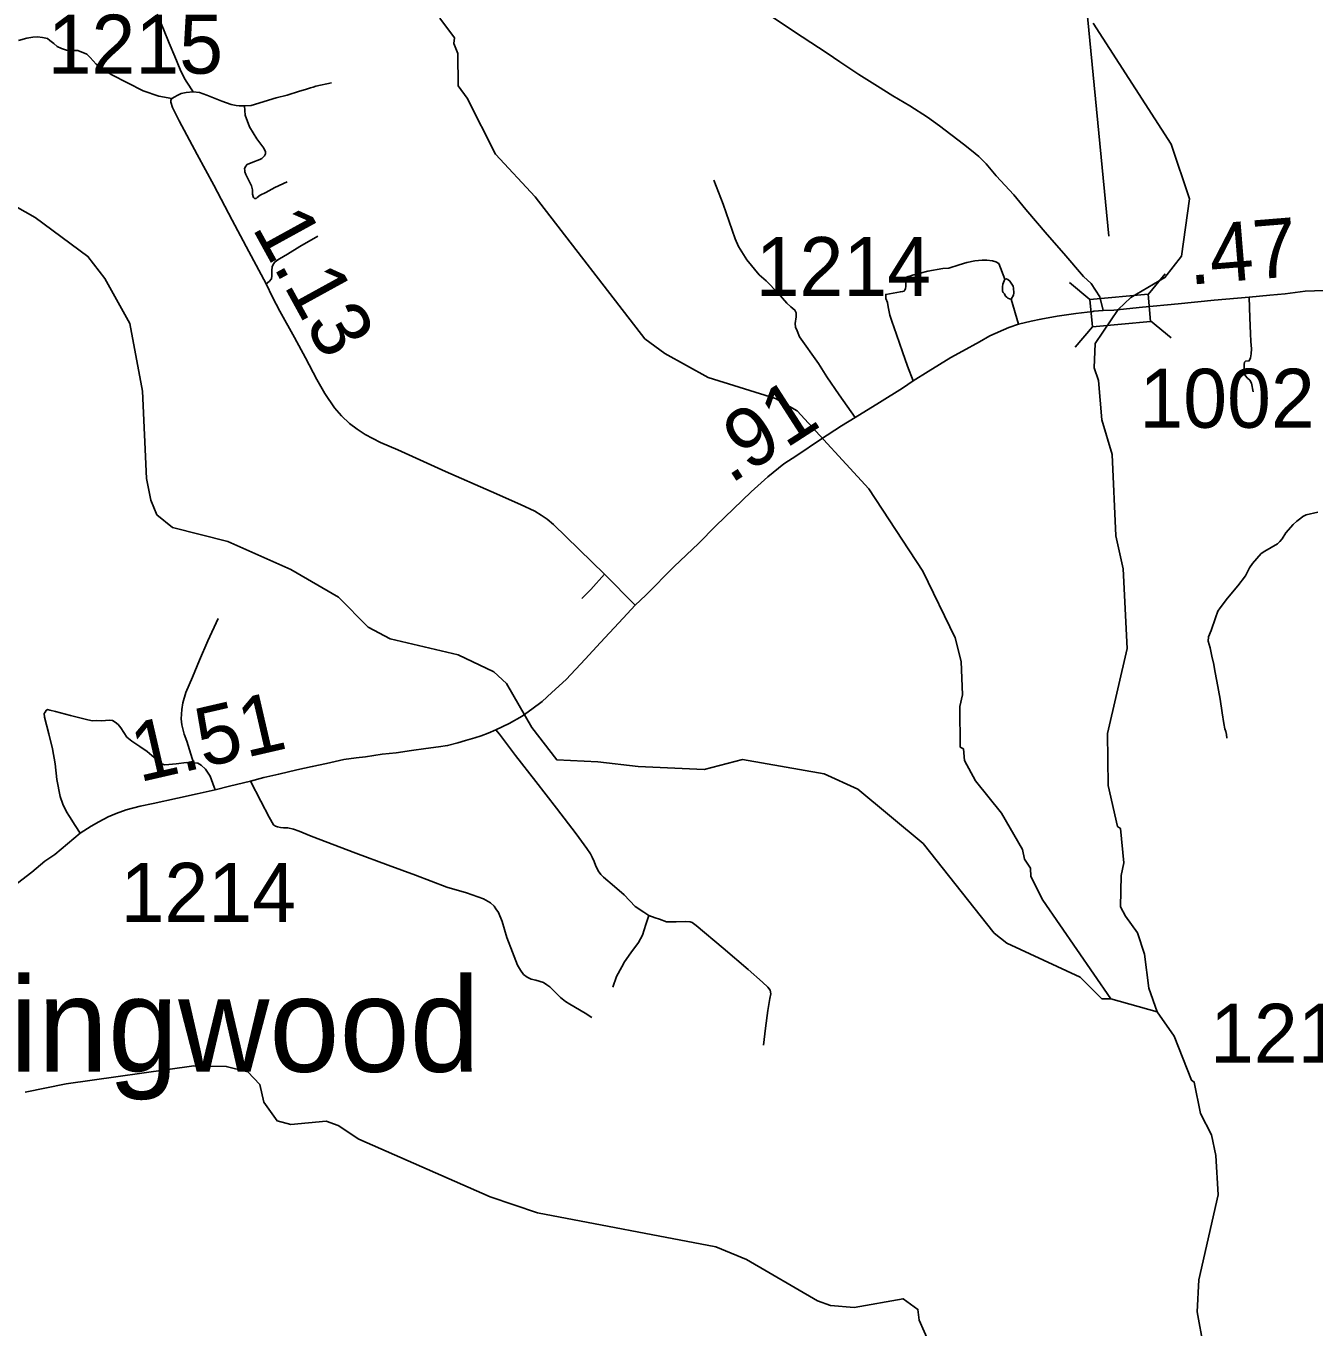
# Model space of a CAD drawing. Extents: x 2290615 to 2522933, y 819489 to 1012715.
# Drawn here: x 2342087 to 2353015, y 894770 to 905808 of the extents above; entities that cross this region are included whole.
import ezdxf

# ---------------------------------------------------------------- set-up
doc = ezdxf.new("R2010")
doc.units = 0
for name, color, linetype in [('Exist Civil Demographics Community Label', 7, 'Continuous'), ('Exist Hydrographic Creek Single Shore', 7, 'Continuous'), ('Exist Hydrographic Misc Water Feature', 7, 'Continuous'), ('Exist Road Non-System Type 51', 7, 'Continuous'), ('Exist Road Secondary Mileage Hundredths English Label', 7, 'Continuous'), ('Exist Road Secondary Structure Standard Bridge CELL', 7, 'Continuous'), ('Exist Road Secondary Structure Standard Bridge Number Label', 7, 'Continuous'), ('Exist Road Secondary Type 51 Attributed', 7, 'Continuous'), ('Exist Road Secondary Type 51 Number Label', 7, 'Continuous')]:
    doc.layers.add(name, color=color, linetype=linetype)

msp = doc.modelspace()

# ---------------------------------------------------------------- linework, layer by layer
at = {"layer": 'Exist Hydrographic Creek Single Shore'}
for points in [[(2351677, 897449), (2351607, 897650), (2351571, 897940), (2351510, 898121), (2351408, 898262), (2351366, 898339), (2351371, 898605), (2351395, 898714), (2351366, 899005), (2351341, 899021), (2351262, 899368), (2351257, 899811), (2351423, 900531), (2351390, 901205), (2351328, 901485), (2351295, 902176), (2351208, 902468), (2351179, 902802), (2351144, 902909), (2351150, 903116), (2351345, 903405), (2351454, 903506), (2351743, 903675), (2351883, 903858), (2351952, 904343), (2351796, 904806), (2351134, 905833)], [(2352206, 894290), (2352102, 894591), (2352069, 894613), (2352015, 894906), (2352029, 895179), (2352195, 895898), (2352174, 896232), (2352139, 896408), (2352045, 896588), (2351992, 896855), (2351967, 896870), (2351820, 897245), (2351677, 897449)], [(2342079, 896770), (2342428, 896840), (2343509, 896993), (2343784, 896987), (2343968, 896942), (2344069, 896835), (2344104, 896685), (2344215, 896526), (2344332, 896494), (2344631, 896523), (2344732, 896485), (2344908, 896370), (2346022, 895881), (2346424, 895747), (2347935, 895457), (2348194, 895350), (2348798, 895000), (2348907, 894959), (2349107, 894944), (2349523, 895017), (2349649, 894927), (2349659, 894835), (2349744, 894645)]]:
    msp.add_lwpolyline(points, dxfattribs=at)
at = {"layer": 'Exist Hydrographic Misc Water Feature'}
msp.add_line((2351677, 897449), (2351284, 897561), dxfattribs=at)
for points in [[(2351284, 897561), (2350707, 898397), (2350605, 898596), (2350604, 898669), (2350553, 898745), (2350535, 898827), (2350357, 899134), (2350137, 899408), (2350043, 899581), (2350034, 899679), (2350008, 899695), (2350004, 900039), (2350028, 900138), (2350016, 900420), (2349964, 900622), (2349690, 901185), (2349232, 901885), (2348624, 902546), (2348440, 902650), (2347871, 902827), (2347502, 903032), (2347334, 903156), (2346403, 904359), (2346066, 904722), (2345827, 905195), (2345751, 905300), (2345747, 905576), (2345713, 905660), (2345720, 905709), (2345594, 905875)], [(2351284, 897561), (2351208, 897561), (2351023, 897744), (2350403, 898033), (2350294, 898118), (2349693, 898877), (2349138, 899337), (2348853, 899467), (2348160, 899589), (2347836, 899504), (2347278, 899530), (2346936, 899569), (2346586, 899587), (2346374, 899861), (2346161, 900233), (2346052, 900333), (2345750, 900478), (2345174, 900612), (2344989, 900710), (2344736, 900965), (2344333, 901201), (2343798, 901439), (2343329, 901557), (2343195, 901664), (2343144, 901789), (2343108, 901972), (2343074, 902712), (2342967, 903285), (2342754, 903667), (2342611, 903855), (2342165, 904185), (2341804, 904387)]]:
    msp.add_lwpolyline(points, dxfattribs=at)
at = {"layer": 'Exist Road Non-System Type 51'}
msp.add_line((2350501, 903280), (2350440, 903491), dxfattribs=at)
msp.add_line((2350501, 903280), (2350440, 903491), dxfattribs=at)
for points in [[(2343199, 905909), (2343253, 905780), (2343300, 905662), (2343349, 905549), (2343393, 905440), (2343430, 905364), (2343450, 905332), (2343504, 905249)], [(2343322, 905193), (2343212, 905214), (2343081, 905258), (2342948, 905325), (2342814, 905395), (2342719, 905454), (2342681, 905485), (2342632, 905541), (2342603, 905570), (2342525, 905601), (2342479, 905601), (2342431, 905602), (2342387, 905616), (2342351, 905635), (2342323, 905659), (2342290, 905684), (2342268, 905702), (2342226, 905712), (2342184, 905717), (2342144, 905713), (2342094, 905704), (2342024, 905685)], [(2343504, 905249), (2343445, 905245), (2343402, 905235), (2343369, 905220), (2343348, 905208), (2343322, 905193)], [(2343504, 905249), (2343445, 905245), (2343402, 905235), (2343369, 905220), (2343348, 905208), (2343322, 905193)], [(2343939, 905130), (2343893, 905131), (2343869, 905133), (2343826, 905143), (2343746, 905170), (2343620, 905222), (2343557, 905244), (2343504, 905249)], [(2343939, 905130), (2343893, 905131), (2343869, 905133), (2343826, 905143), (2343746, 905170), (2343620, 905222), (2343557, 905244), (2343504, 905249)], [(2344677, 905326), (2344544, 905298), (2344520, 905289), (2344499, 905284), (2344456, 905269), (2344405, 905256), (2344301, 905223), (2344208, 905198), (2343995, 905133), (2343939, 905130)], [(2344677, 905326), (2344544, 905298), (2344520, 905289), (2344499, 905284), (2344456, 905269), (2344405, 905256), (2344301, 905223), (2344208, 905198), (2343995, 905133), (2343939, 905130)], [(2343322, 905193), (2343315, 905180), (2343314, 905163), (2343328, 905116)], [(2343322, 905193), (2343315, 905180), (2343314, 905163), (2343328, 905116)], [(2344300, 904487), (2344197, 904440), (2344119, 904397), (2344072, 904373), (2344048, 904353), (2344038, 904347), (2344031, 904346), (2344023, 904347), (2344016, 904353), (2344012, 904364), (2344006, 904382), (2344006, 904420), (2343998, 904453), (2343977, 904498), (2343951, 904549), (2343943, 904571), (2343941, 904586), (2343940, 904598), (2343948, 904618), (2343961, 904634), (2344010, 904655), (2344068, 904676), (2344086, 904686), (2344100, 904698), (2344108, 904706), (2344113, 904712), (2344118, 904725), (2344118, 904742), (2344102, 904772), (2344045, 904852), (2343981, 904953), (2343944, 905051), (2343939, 905130)], [(2347917, 904502), (2347997, 904299), (2348100, 904005), (2348128, 903939), (2348199, 903827), (2348302, 903699), (2348362, 903649), (2348465, 903543), (2348537, 903457), (2348572, 903426), (2348606, 903399), (2348616, 903377), (2348615, 903343), (2348607, 903287), (2348610, 903255), (2348624, 903223), (2348646, 903174), (2348807, 902946), (2348875, 902834), (2348980, 902681), (2349117, 902489)], [(2344561, 904026), (2344407, 903940), (2344305, 903873), (2344235, 903834), (2344212, 903819), (2344196, 903806), (2344185, 903792), (2344175, 903765), (2344171, 903735), (2344171, 903690), (2344167, 903665), (2344148, 903643), (2344122, 903621)], [(2350386, 903662), (2350334, 903794), (2350310, 903809), (2350282, 903817), (2350234, 903822), (2350192, 903824), (2350132, 903817), (2350064, 903804), (2349997, 903783), (2349911, 903755), (2349859, 903752), (2349733, 903730), (2349602, 903695), (2349581, 903687), (2349567, 903684), (2349553, 903678), (2349548, 903675), (2349545, 903671), (2349544, 903661), (2349545, 903646), (2349546, 903625), (2349547, 903602), (2349542, 903580), (2349538, 903570), (2349532, 903561), (2349519, 903557), (2349500, 903555), (2349438, 903542), (2349376, 903533), (2349378, 903499), (2349391, 903464), (2349395, 903426), (2349410, 903357), (2349427, 903307), (2349467, 903193), (2349517, 903045), (2349561, 902924), (2349609, 902799)], [(2350386, 903662), (2350369, 903620), (2350367, 903596), (2350365, 903578), (2350365, 903560), (2350370, 903548), (2350382, 903536), (2350392, 903518), (2350402, 903508), (2350410, 903500), (2350426, 903495), (2350440, 903491)], [(2350386, 903662), (2350369, 903620), (2350367, 903596), (2350365, 903578), (2350365, 903560), (2350370, 903548), (2350382, 903536), (2350392, 903518), (2350402, 903508), (2350410, 903500), (2350426, 903495), (2350440, 903491)], [(2350440, 903491), (2350458, 903527), (2350461, 903547), (2350459, 903585), (2350457, 903603), (2350440, 903629), (2350428, 903645), (2350410, 903659), (2350398, 903664), (2350386, 903662)], [(2350440, 903491), (2350458, 903527), (2350461, 903547), (2350459, 903585), (2350457, 903603), (2350440, 903629), (2350428, 903645), (2350410, 903659), (2350398, 903664), (2350386, 903662)], [(2352457, 903508), (2352462, 903335), (2352468, 903201), (2352470, 903132), (2352476, 903071), (2352475, 903029), (2352468, 902995), (2352458, 902970), (2352426, 902967), (2352418, 902958), (2352416, 902938), (2352415, 902910), (2352415, 902871), (2352422, 902844), (2352444, 902821), (2352463, 902805), (2352477, 902781), (2352491, 902706)], [(2353040, 901687), (2352941, 901665), (2352912, 901649), (2352894, 901635), (2352862, 901611), (2352830, 901582), (2352769, 901511), (2352738, 901461), (2352716, 901439), (2352696, 901417), (2352591, 901355), (2352559, 901335), (2352484, 901252), (2352459, 901214), (2352426, 901147), (2352361, 901061), (2352272, 900956), (2352210, 900874), (2352191, 900847), (2352172, 900790), (2352135, 900684), (2352111, 900629), (2352110, 900594), (2352127, 900536), (2352141, 900466), (2352157, 900394), (2352166, 900342), (2352184, 900253), (2352211, 900102), (2352228, 899986), (2352243, 899895), (2352252, 899848), (2352259, 899826), (2352264, 899801), (2352267, 899770)], [(2346990, 901160), (2346876, 901032), (2346799, 900955)], [(2343507, 899562), (2343449, 899744), (2343429, 899804), (2343408, 899882), (2343403, 899935), (2343408, 900013), (2343417, 900070), (2343442, 900158), (2343497, 900288), (2343559, 900431), (2343629, 900596), (2343717, 900785)], [(2343507, 899562), (2343449, 899744), (2343429, 899804), (2343408, 899882), (2343403, 899935), (2343408, 900013), (2343417, 900070), (2343442, 900158), (2343497, 900288), (2343559, 900431), (2343629, 900596), (2343717, 900785)], [(2343507, 899562), (2343447, 899563), (2343361, 899554), (2343298, 899546), (2343262, 899544), (2343223, 899558), (2343172, 899605), (2343114, 899657), (2343052, 899700), (2342985, 899745), (2342943, 899780), (2342890, 899859), (2342868, 899885), (2342844, 899905), (2342821, 899921), (2342793, 899922), (2342729, 899918), (2342681, 899919), (2342649, 899918), (2342589, 899932), (2342465, 899962), (2342338, 899997), (2342288, 900008), (2342268, 900012), (2342258, 900006), (2342249, 899992), (2342241, 899978), (2342243, 899948), (2342279, 899806), (2342312, 899681), (2342334, 899553), (2342348, 899419), (2342377, 899275), (2342400, 899212), (2342429, 899146), (2342455, 899105), (2342504, 899029), (2342547, 898964)], [(2343507, 899562), (2343447, 899563), (2343361, 899554), (2343298, 899546), (2343262, 899544), (2343223, 899558), (2343172, 899605), (2343114, 899657), (2343052, 899700), (2342985, 899745), (2342943, 899780), (2342890, 899859), (2342868, 899885), (2342844, 899905), (2342821, 899921), (2342793, 899922), (2342729, 899918), (2342681, 899919), (2342649, 899918), (2342589, 899932), (2342465, 899962), (2342338, 899997), (2342288, 900008), (2342268, 900012), (2342258, 900006), (2342249, 899992), (2342241, 899978), (2342243, 899948), (2342279, 899806), (2342312, 899681), (2342334, 899553), (2342348, 899419), (2342377, 899275), (2342400, 899212), (2342429, 899146), (2342455, 899105), (2342504, 899029), (2342547, 898964)], [(2347368, 898268), (2347324, 898295), (2347251, 898344), (2347158, 898443), (2347077, 898514), (2346984, 898591), (2346960, 898613), (2346939, 898646), (2346915, 898694), (2346903, 898724), (2346888, 898762), (2346872, 898790), (2346843, 898835), (2346750, 898958), (2346585, 899176), (2346409, 899404), (2346236, 899622), (2346101, 899803), (2346071, 899842)], [(2343690, 899332), (2343672, 899387), (2343647, 899447), (2343608, 899507), (2343572, 899540), (2343543, 899559), (2343507, 899562)], [(2346884, 897402), (2346828, 897439), (2346697, 897514), (2346661, 897537), (2346619, 897571), (2346529, 897662), (2346503, 897679), (2346473, 897699), (2346409, 897718), (2346371, 897726), (2346337, 897743), (2346304, 897767), (2346278, 897803), (2346255, 897846), (2346212, 897956), (2346164, 898081), (2346125, 898217), (2346094, 898292), (2346070, 898324), (2346055, 898346), (2346025, 898374), (2345965, 898407), (2345822, 898459), (2345656, 898507), (2345388, 898608), (2345157, 898693), (2344882, 898794), (2344505, 898939), (2344404, 898982), (2344354, 898999), (2344306, 899011), (2344270, 899010), (2344244, 899014), (2344220, 899018), (2344202, 899023), (2344186, 899035), (2344147, 899101), (2344077, 899236), (2343991, 899407)], [(2346884, 897402), (2346828, 897439), (2346697, 897514), (2346661, 897537), (2346619, 897571), (2346529, 897662), (2346503, 897679), (2346473, 897699), (2346409, 897718), (2346371, 897726), (2346337, 897743), (2346304, 897767), (2346278, 897803), (2346255, 897846), (2346212, 897956), (2346164, 898081), (2346125, 898217), (2346094, 898292), (2346070, 898324), (2346055, 898346), (2346025, 898374), (2345965, 898407), (2345822, 898459), (2345656, 898507), (2345388, 898608), (2345157, 898693), (2344882, 898794), (2344505, 898939), (2344404, 898982), (2344354, 898999), (2344306, 899011), (2344270, 899010), (2344244, 899014), (2344220, 899018), (2344202, 899023), (2344186, 899035), (2344147, 899101), (2344077, 899236), (2343991, 899407)], [(2347368, 898268), (2347343, 898191), (2347314, 898101), (2347279, 898037), (2347214, 897950), (2347161, 897873), (2347137, 897831), (2347094, 897749), (2347063, 897660)], [(2347368, 898268), (2347343, 898191), (2347314, 898101), (2347279, 898037), (2347214, 897950), (2347161, 897873), (2347137, 897831), (2347094, 897749), (2347063, 897660)], [(2348339, 897168), (2348355, 897312), (2348377, 897462), (2348392, 897564), (2348402, 897604), (2348397, 897634), (2348377, 897660), (2348330, 897702), (2348209, 897808), (2347997, 897989), (2347769, 898183), (2347736, 898206), (2347717, 898214), (2347682, 898215), (2347598, 898213), (2347556, 898212), (2347518, 898213), (2347458, 898235), (2347420, 898248), (2347368, 898268)], [(2348339, 897168), (2348355, 897312), (2348377, 897462), (2348392, 897564), (2348402, 897604), (2348397, 897634), (2348377, 897660), (2348330, 897702), (2348209, 897808), (2347997, 897989), (2347769, 898183), (2347736, 898206), (2347717, 898214), (2347682, 898215), (2347598, 898213), (2347556, 898212), (2347518, 898213), (2347458, 898235), (2347420, 898248), (2347368, 898268)]]:
    msp.add_lwpolyline(points, dxfattribs=at)
at = {"layer": 'Exist Road Secondary Structure Standard Bridge CELL'}
for p, q in [((2351600, 903533), (2351745, 903707)), ((2350933, 903634), (2351107, 903489)), ((2350983, 903085), (2351128, 903258)), ((2351621, 903308), (2351795, 903163))]:
    msp.add_line(p, q, dxfattribs=at)
msp.add_lwpolyline([(2351107, 903489), (2351600, 903534), (2351621, 903303), (2351128, 903258)], close=True, dxfattribs=at)
at = {"layer": 'Exist Road Secondary Structure Standard Bridge Number Label'}
msp.add_lwpolyline([(2351267, 904026), (2351050, 906271), (2345693, 911628)], dxfattribs=at)
at = {"layer": 'Exist Road Secondary Type 51 Attributed'}
for points in [[(2347791, 906300), (2348666, 905717), (2348878, 905577), (2348986, 905503), (2349148, 905397), (2349305, 905299), (2349436, 905216), (2349581, 905130), (2349730, 905034), (2349833, 904963), (2350035, 904806), (2350104, 904753), (2350165, 904702), (2350227, 904639), (2350312, 904538), (2350461, 904378), (2350564, 904251), (2350744, 904041), (2350886, 903879), (2351052, 903683), (2351118, 903625), (2351191, 903511), (2351219, 903397)], [(2347250, 900898), (2346990, 901160), (2346560, 901583), (2346506, 901627), (2346455, 901662), (2346400, 901694), (2346278, 901751), (2346031, 901862), (2345643, 902032), (2345426, 902131), (2345240, 902215), (2345093, 902278), (2345026, 902311), (2344961, 902345), (2344895, 902390), (2344830, 902439), (2344762, 902503), (2344703, 902571), (2344619, 902693), (2344552, 902810), (2344457, 902996), (2344363, 903167), (2344239, 903390), (2344178, 903508), (2344122, 903621), (2343977, 903895), (2343835, 904163), (2343678, 904459), (2343537, 904720), (2343386, 905004), (2343328, 905116)], [(2351311, 903399), (2351554, 903424), (2351854, 903452), (2352161, 903484), (2352457, 903508), (2352632, 903527), (2352763, 903538), (2352931, 903561), (2353089, 903565), (2353216, 903564), (2353304, 903561), (2353385, 903554), (2353467, 903539), (2353535, 903528), (2353593, 903513), (2353673, 903489), (2353779, 903459)], [(2351219, 903397), (2351141, 903391), (2351131, 903389), (2350987, 903371), (2350828, 903348), (2350692, 903322), (2350610, 903307), (2350501, 903280), (2350419, 903251), (2350258, 903180), (2350172, 903130), (2350027, 903050), (2349927, 902997), (2349736, 902878), (2349609, 902799), (2349517, 902738), (2349322, 902615), (2349117, 902489), (2349002, 902417), (2348822, 902303), (2348622, 902167), (2348512, 902097), (2348376, 901986), (2348235, 901859), (2348084, 901714), (2347934, 901571), (2347787, 901420), (2347582, 901225), (2347342, 900984), (2347250, 900898)], [(2351219, 903397), (2351311, 903399)], [(2347250, 900898), (2347151, 900787), (2346958, 900582), (2346828, 900439), (2346667, 900267), (2346546, 900158), (2346462, 900080), (2346376, 900016), (2346292, 899957), (2346184, 899894), (2346071, 899842), (2346006, 899813), (2345946, 899790), (2345892, 899772), (2345812, 899751), (2345748, 899730), (2345661, 899708), (2345583, 899696), (2345478, 899683), (2345355, 899666), (2345224, 899646), (2345107, 899635), (2344966, 899613), (2344885, 899604), (2344781, 899588), (2344635, 899556), (2344513, 899529), (2344382, 899501), (2344230, 899466), (2344103, 899436), (2343991, 899407), (2343812, 899363), (2343690, 899332), (2343537, 899297), (2343371, 899261), (2343165, 899217), (2343056, 899193), (2342936, 899162), (2342851, 899131), (2342783, 899102), (2342704, 899062), (2342638, 899025), (2342547, 898964), (2342330, 898785), (2342247, 898726), (2342137, 898635), (2341977, 898513)]]:
    msp.add_lwpolyline(points, dxfattribs=at)

# ---------------------------------------------------------------- texts
at = {"layer": 'Exist Civil Demographics Community Label'}
msp.add_text('Ringwood', height=800, rotation=360, dxfattribs=at).set_placement((2341177, 896942))
at = {"layer": 'Exist Road Secondary Mileage Hundredths English Label'}
for s, rotation, p in [('1.13', 298.7977, (2343999, 904098)), ('.47', 4.6787, (2351953, 903614)), ('.91', 32.7496, (2348058, 901920)), ('1.51', 13.0019, (2343047, 899395))]:
    msp.add_text(s, height=500, rotation=rotation, dxfattribs=at).set_placement(p)
at = {"layer": 'Exist Road Secondary Type 51 Number Label'}
for s, p in [('1215', (2342270, 905404)), ('1214', (2348273, 903519)), ('1002', (2351526, 902402)), ('1214', (2342888, 898213)), ('1217', (2352125, 897018))]:
    msp.add_text(s, height=500, rotation=360, dxfattribs=at).set_placement(p)

doc.saveas('drawing.dxf')
